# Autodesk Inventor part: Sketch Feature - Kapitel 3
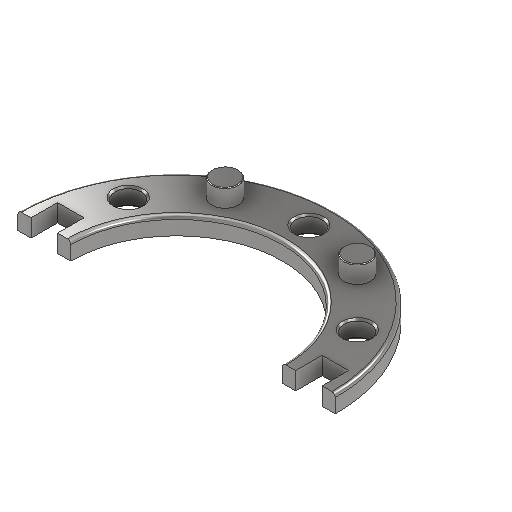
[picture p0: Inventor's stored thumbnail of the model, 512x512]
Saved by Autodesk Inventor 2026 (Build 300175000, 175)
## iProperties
Created: 2022-01
Part Number: Sketch Feature - Kapitel 3
Material: Steel, Mild
Document SubType Name: Modeling
Designer: Lars Bertram Pedersen
Density: 7.85 g/cm^3
Appearance: Semi-Polished
Mass: 62.6659 g
Surface Area: 49.6584 cm^2
Volume: 7.98292 cm^3
Author: Lars Bertram Pedersen
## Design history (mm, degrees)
sketch "Sketch1"
  geometry: L1 (-45, 0)-(-30, 0); L2 (30, 0)-(45, 0); L3 (-63, 0)-(63, 0) reference; A1 r 45 centre (0, 0) between (45, 0) and (-45, 0); A2 r 30 centre (0, 0) between (30, 0) and (-30, 0); 1 further point
  constraints: 4 end point, 4 point on circle, 2 centre point, 2 coincident, 2 collinear, 2 horizontal
  dimensions: "d0" = 30 radius of A2; "d1" = 45 radius of A1
extrude "Extrusion1" new body sketch "Sketch1" distance "d2" = 5; taper "d3" = 0 deg
sketch "Sketch3"
  geometry: L1 (0, 0)-(15, 0) reference; L2 (15, 0)-(15, 5) reference; L3 (0, 5)-(15, 5) reference; L4 (0, 0)-(0, 5) reference; L5 (3.75, 0)-(11.25, 0); L6 (11.25, 0)-(11.25, 5); L7 (11.25, 5)-(3.75, 5); L8 (3.75, 5)-(3.75, 0); 2 further points
  constraints: 8 end point, 2 midpoint, 2 parallel, 2 point on line, 1 horizontal, 1 perpendicular
  dimensions: "d8" = 7.5 distance of L6.end L7.end
extrude "Extrusion3" cut sketch "Sketch3" distance "d9" = 7.5; taper "d10" = 0 deg
mirror "Mirror1"
sketch "Sketch5" dims "d15" = 75 (= d0 + d1)
  geometry: L1 (-41.25, 0)-(-41.25, 7.5) reference; C1 r 3.75 at (-37.5, 0); C2 r 3.75 at (-32.476, -18.75); C3 r 3.75 at (-18.75, -32.476); C4 r 3.75 at (0, -37.5); C5 r 3.75 at (18.75, -32.476); C6 r 3.75 at (32.476, -18.75); C7 r 3.75 at (37.5, 0); C8 r 3.75 at (32.476, 18.75); C9 r 3.75 at (18.75, 32.476); C10 r 3.75 at (0, 37.5); C11 r 3.75 at (-18.75, 32.476); C12 r 3.75 at (-32.476, 18.75); 5 further points
  constraints: 12 centre point, 4 coincident, 2 horizontal alignment, 27 other
  dimensions: "d16" = 7.5 diameter of C1; "d19" = 360 deg dimension on point (0, 0) C1.centre (derived)
extrude "Extrusion5" join sketch "Sketch5" distance "d21" = 5; taper "d22" = 0 deg
hole "Hole1" sketch "Sketch5" diameter "d23" = 7.5; stored, may be unused: countersink angle "d27" = 90 deg, drill point angle "d29" = 118 deg; dims "d24" = 6, "d25" = 4, "d26" = 2, "d28" = 8
chamfer "Chamfer1" distance "d30" = 0.5; stored, may be unused: second distance "d31" = 2, angle "d32" = 45 deg
fillet "Fillet1" dims "d33" = 0.2, "d35" = 1
body "Solid1"
node "Projected Loop1"
node "Sketch Circular Pattern1" dims "d19" = 360 deg (derived)
